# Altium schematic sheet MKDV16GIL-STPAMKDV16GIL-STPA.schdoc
size 127 x 101 mm
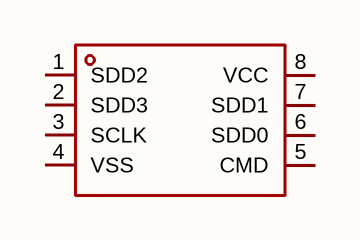
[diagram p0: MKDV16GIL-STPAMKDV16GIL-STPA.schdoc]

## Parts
U?  mkdv16gil-stpa  [LGA-8_L8.0-W6.6-P1.27-TL-MKDV32GIL-STPB]  (value not drawn)

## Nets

Not connected (* = marked no-connect by the designer): U? 1(SDD2) 2(SDD3) 3(SCLK) 4(VSS) 5(CMD) 6(SDD0) 7(SDD1) 8(VCC)

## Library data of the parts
U? = mkdv16gil-stpa: 存储容量:16Gbit;时钟频率(fc):50MHz;工作电压:2.7V~3.6V;; Manufacturer: MK(米客方德); AddInBom: yes; Memory Size: 16Gbit; Interface: SD接口；SPI; Clock Frequency: 50MHz; Standby Supply Current: 250uA; Program / Erase Cycles: 3万次; ECC: 有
